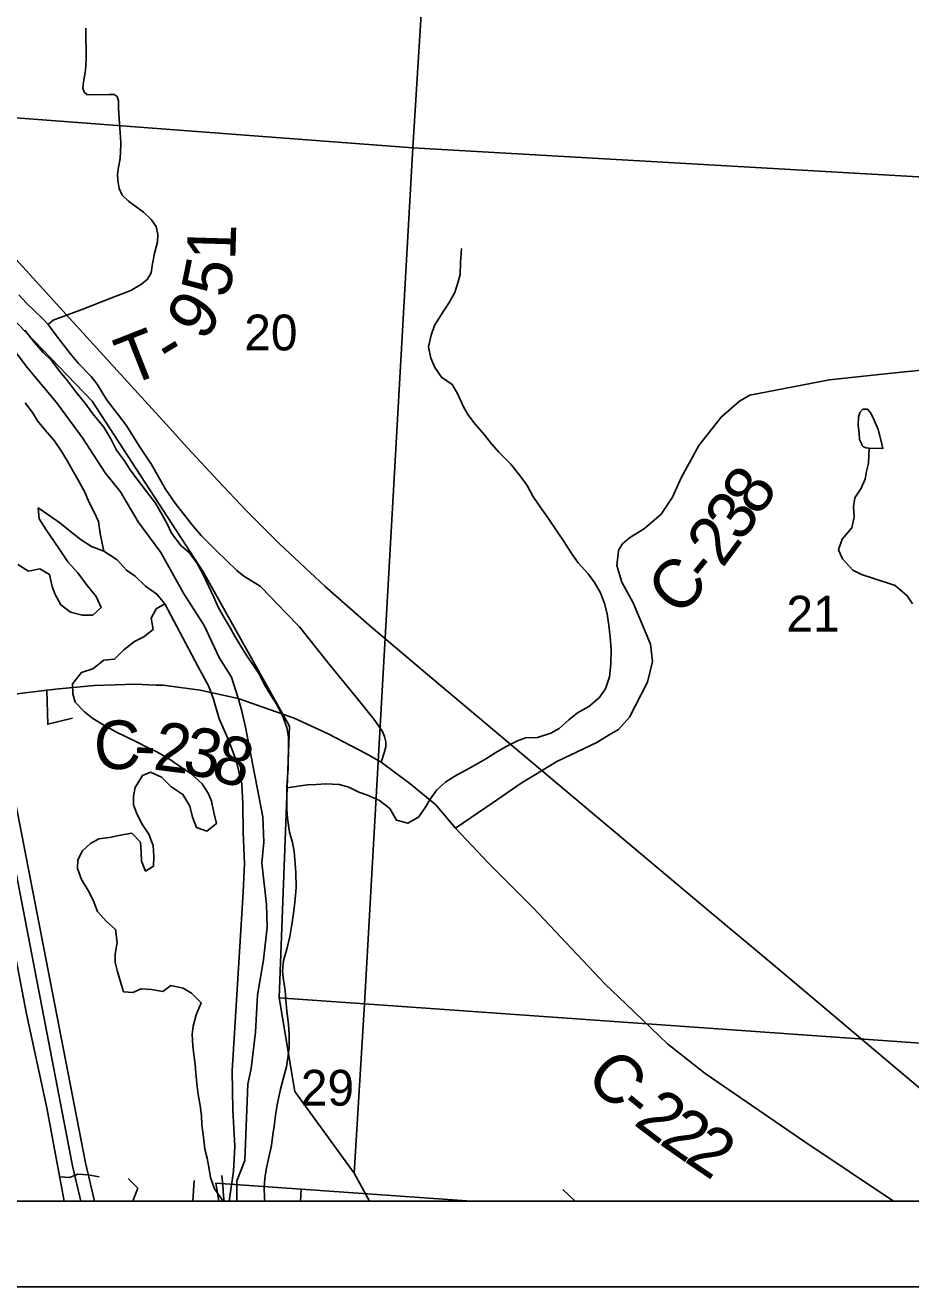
# Model space of a CAD drawing. Extents: x 0 to 34, y 0 to 22.
# Drawn here: x 6.981 to 8.016, y 14 to 15.475 of the extents above; entities that cross this region are included whole.
import ezdxf

# ---------------------------------------------------------------- set-up
doc = ezdxf.new("R2010")
doc.units = 0
for name, color, linetype in [('GM_X_Corporation', 7, 'Continuous'), ('GM_X_County_Road', 7, 'Continuous'), ('GM_X_County_Road_Text', 7, 'Continuous'), ('GM_X_Major_River', 7, 'Continuous'), ('GM_X_Minor_Lake', 7, 'Continuous'), ('GM_X_Minor_River', 7, 'Continuous'), ('GM_X_Rail_Line', 7, 'Continuous'), ('GM_X_Section_Text', 7, 'Continuous'), ('GM_X_Township_Road', 7, 'Continuous'), ('GM_X_Township_Road_Text', 7, 'Continuous'), ('GM_X_US_Route', 7, 'Continuous'), ('SH_Data', 7, 'Continuous')]:
    doc.layers.add(name, color=color, linetype=linetype)

msp = doc.modelspace()

# ---------------------------------------------------------------- linework, layer by layer
at = {"layer": 'GM_X_Corporation'}
for p, q in [((7.1768, 14.1), (7.1783, 14.1242)), ((7.1783, 14.1242), (7.1768, 14.1)), ((7.3032, 14.114), (7.2036, 14.1213)), ((7.3032, 14.114), (7.2036, 14.1213)), ((7.2036, 14.1213), (7.2071, 14.1)), ((7.3024, 14.1), (7.3032, 14.114)), ((7.3032, 14.114), (7.3024, 14.1)), ((7.3032, 14.114), (7.5024, 14.1)), ((7.5024, 14.1), (7.3032, 14.114)), ((2.1, 14.1), (7.1768, 14.1)), ((7.1768, 14.1), (8.9, 14.1)), ((7.2071, 14.1), (7.3024, 14.1)), ((7.3024, 14.1), (7.5024, 14.1)), ((7.5024, 14.1), (8.3035, 14.1))]:
    msp.add_line(p, q, dxfattribs=at)
for points in [[(6.463, 16.4089), (7.4964, 16.3324), (7.434, 15.3319), (6.4021, 15.41)], [(7.4964, 16.3324), (8.4813, 16.2644), (8.4262, 15.2749), (7.434, 15.3319)], [(6.4021, 15.41), (7.434, 15.3319), (7.3773, 14.3307), (7.2777, 14.338), (7.2898, 14.6557), (7.1888, 14.8361), (7.0591, 15.0356), (6.8563, 15.2461), (6.757, 15.3231), (6.6096, 15.301), (6.3846, 15.1464)], [(7.434, 15.3319), (8.4262, 15.2749), (8.3747, 14.2604), (7.3773, 14.3307)], [(7.2777, 14.338), (7.3773, 14.3307), (7.3654, 14.1329), (7.2958, 14.2282)], [(7.3832, 14.1), (8.3589, 14.1), (8.3747, 14.2604), (7.3773, 14.3307), (7.3654, 14.1329)]]:
    msp.add_lwpolyline(points, close=True, dxfattribs=at)
for points in [[(2.1, 14.1), (7.2283, 14.1), (7.228, 14.124), (7.2373, 14.1475), (7.241, 14.237), (7.2449, 14.2552), (7.2498, 14.2976), (7.2524, 14.3409), (7.2595, 14.3825), (7.2636, 14.4204), (7.263, 14.447), (7.2573, 14.4956), (7.2598, 14.5199), (7.2585, 14.5495), (7.2381, 14.6544), (7.2337, 14.6749), (7.2295, 14.6885), (7.2219, 14.7129), (7.2077, 14.7351), (7.1899, 14.7732), (7.1659, 14.8113), (7.1391, 14.8586), (7.1129, 14.8944), (7.092, 14.9295), (7.074, 14.9517), (7.0478, 14.9929), (7.0171, 15.0341), (6.9834, 15.0746), (6.9489, 15.1197)], [(6.9489, 15.1197), (6.9834, 15.0746), (7.0171, 15.0341), (7.0478, 14.9929), (7.074, 14.9517), (7.092, 14.9295), (7.1129, 14.8944), (7.1391, 14.8586), (7.1659, 14.8113), (7.1899, 14.7732), (7.2077, 14.7351), (7.2219, 14.7129), (7.2295, 14.6885), (7.2337, 14.6749), (7.2381, 14.6544), (7.2585, 14.5495), (7.2598, 14.5199), (7.2573, 14.4956), (7.263, 14.447), (7.2636, 14.4204), (7.2595, 14.3825), (7.2524, 14.3409), (7.2498, 14.2976), (7.2449, 14.2552), (7.241, 14.237), (7.2373, 14.1475), (7.228, 14.124), (7.2283, 14.1), (8.9, 14.1)], [(3.0991, 14.1), (7.0261, 14.1), (7.0059, 14.2093), (6.982, 14.3191), (6.9581, 14.4456)]]:
    msp.add_lwpolyline(points, dxfattribs=at)
at = {"layer": 'GM_X_County_Road'}
for points in [[(6.9731, 15.1602), (6.982, 15.1504), (7.0016, 15.1315), (7.0074, 15.1252), (7.0161, 15.1137), (7.033, 15.0914), (7.0431, 15.0796), (7.0577, 15.0645), (7.0649, 15.0555), (7.0703, 15.0466), (7.0756, 15.0376), (7.0988, 15.0075), (7.1151, 14.9817), (7.1284, 14.9618), (7.1446, 14.9326), (7.156, 14.9163), (7.1756, 14.8915), (7.1865, 14.8785), (7.2041, 14.8612), (7.228, 14.8378), (7.2365, 14.831), (7.2556, 14.8193), (7.268, 14.8063), (7.2851, 14.7885), (7.3013, 14.7716), (7.3102, 14.7605), (7.3362, 14.7283), (7.3678, 14.6895), (7.3887, 14.6635), (7.3983, 14.6493), (7.4009, 14.6435), (7.4023, 14.6374), (7.4022, 14.6313), (7.4005, 14.6246), (7.3969, 14.6136)], [(7.6745, 14.8605), (7.6746, 14.8614), (7.6791, 14.8687), (7.6873, 14.8757), (7.705, 14.8866), (7.7245, 14.9036), (7.7378, 14.9236), (7.7477, 14.9461), (7.7684, 14.9837), (7.7945, 15.0171), (7.8159, 15.0357), (7.8283, 15.0427), (7.9213, 15.0605), (7.9902, 15.068), (8.0364, 15.0729), (8.0666, 15.0814), (8.0809, 15.0888), (8.1031, 15.1051), (8.1203, 15.1183)], [(7.6636, 14.6453), (7.6747, 14.6519), (7.6874, 14.6662), (7.7084, 14.7071), (7.7141, 14.7311), (7.7119, 14.7516), (7.6915, 14.7998), (7.6786, 14.8239), (7.6726, 14.8436), (7.6745, 14.8605)], [(6.9681, 14.693), (7.006, 14.6976), (7.02, 14.6993)], [(7.02, 14.6993), (7.0243, 14.6998), (7.0617, 14.703), (7.1094, 14.7047), (7.1338, 14.7037)], [(7.1338, 14.7037), (7.142, 14.7034), (7.1852, 14.6976), (7.2297, 14.688), (7.2753, 14.672)], [(7.2753, 14.672), (7.2951, 14.6651), (7.3343, 14.6472), (7.3797, 14.6231), (7.3969, 14.6136)], [(7.5753, 14.598), (7.6024, 14.6143), (7.6491, 14.6367), (7.6636, 14.6453)], [(7.3969, 14.6136), (7.4303, 14.5887), (7.4607, 14.5637), (7.4837, 14.5365)], [(7.4837, 14.5365), (7.5269, 14.5657), (7.5618, 14.5898), (7.5753, 14.598)], [(7.4837, 14.5365), (7.523, 14.495), (7.5746, 14.4431), (7.6585, 14.3541), (7.6835, 14.3304)], [(7.6835, 14.3304), (7.732, 14.2843), (7.7758, 14.2493), (7.8923, 14.1696), (7.9962, 14.1)]]:
    msp.add_lwpolyline(points, dxfattribs=at)
at = {"layer": 'GM_X_Major_River'}
for p, q in [((7.0215, 14.1284), (7.0325, 14.1277)), ((7.0325, 14.1277), (7.042, 14.1318)), ((7.042, 14.1318), (7.0541, 14.131)), ((7.0541, 14.131), (7.0673, 14.1287)), ((7.101, 14.1268), (7.1124, 14.1154)), ((7.2116, 14.1187), (7.2104, 14.1301)), ((7.1124, 14.1154), (7.1067, 14.1014)), ((7.2127, 14.1058), (7.2116, 14.1187)), ((7.2134, 14.1), (7.2127, 14.1058)), ((7.1067, 14.1014), (7.1063, 14.1))]:
    msp.add_line(p, q, dxfattribs=at)
for points in [[(7.2607, 14.1), (7.2606, 14.1038), (7.2602, 14.1159), (7.261, 14.1265), (7.2625, 14.1372), (7.2652, 14.1497), (7.2686, 14.1652), (7.2702, 14.1781), (7.2717, 14.1879), (7.2733, 14.2004), (7.2752, 14.2126), (7.279, 14.2311), (7.2832, 14.2459), (7.2862, 14.2573), (7.2882, 14.2705), (7.2893, 14.2804), (7.2893, 14.2944), (7.2886, 14.3073), (7.2867, 14.3225), (7.2856, 14.3354), (7.2845, 14.3467), (7.2827, 14.3585), (7.2815, 14.3691), (7.2827, 14.3816), (7.2865, 14.3949), (7.29, 14.4096), (7.2926, 14.4237), (7.2945, 14.4366), (7.2957, 14.4464), (7.2969, 14.4574), (7.2976, 14.4673), (7.2973, 14.4839), (7.2962, 14.4949), (7.2951, 14.509), (7.2932, 14.5196), (7.2898, 14.5317), (7.2872, 14.548), (7.2865, 14.5582), (7.2865, 14.5836), (7.2873, 14.5965), (7.2881, 14.606), (7.2881, 14.6178), (7.2885, 14.6272), (7.2885, 14.6428), (7.2867, 14.6542), (7.2814, 14.6682), (7.2742, 14.6822), (7.2678, 14.6917), (7.2603, 14.7039), (7.2539, 14.7171), (7.2475, 14.7266), (7.2399, 14.738), (7.2316, 14.7513), (7.2256, 14.7608), (7.2199, 14.7714), (7.2128, 14.7831), (7.2063, 14.7949), (7.2011, 14.8063), (7.195, 14.8199), (7.1886, 14.8328), (7.1819, 14.8457), (7.1728, 14.8583), (7.163, 14.8666), (7.1516, 14.8814), (7.1468, 14.8924), (7.1407, 14.9027), (7.1328, 14.9163), (7.1226, 14.93), (7.1124, 14.9433), (7.1026, 14.9565), (7.0966, 14.966), (7.0875, 14.9785), (7.0807, 14.9918), (7.0724, 15.0051), (7.0596, 15.0207), (7.0505, 15.0336), (7.04, 15.0468), (7.0305, 15.059), (7.0211, 15.0704), (7.0113, 15.0833), (7.0018, 15.0928), (6.9916, 15.1042), (6.9803, 15.1186)], [(7.0725, 14.8603), (7.0684, 14.8809), (7.0665, 14.8948), (7.0612, 14.9058), (7.0556, 14.9172), (7.0499, 14.9301), (7.042, 14.9441), (7.036, 14.9551), (7.0299, 14.9654), (7.0228, 14.9775), (7.0145, 14.9896), (7.0039, 15.0018), (6.9948, 15.0128), (6.9892, 15.0223), (6.9805, 15.0337)], [(6.9969, 14.8979), (6.9958, 14.9108), (7.0082, 14.9024), (7.0211, 14.8933), (7.0335, 14.8831), (7.046, 14.8736), (7.0581, 14.8656), (7.0725, 14.8603)], [(6.9718, 14.8445), (6.9846, 14.8369), (6.9979, 14.8395), (7.0092, 14.8331), (7.0122, 14.819), (7.0156, 14.8096), (7.0224, 14.7974), (7.0337, 14.7891), (7.0473, 14.7856), (7.0598, 14.7856), (7.0693, 14.7943), (7.0637, 14.8072), (7.052, 14.8216), (7.0422, 14.8349), (7.0304, 14.8478), (7.021, 14.8619), (7.0146, 14.8717), (7.0052, 14.8854), (6.9969, 14.8979)], [(7.0725, 14.8603), (7.088, 14.85), (7.0989, 14.8379), (7.1091, 14.831), (7.1212, 14.8193), (7.1345, 14.8098), (7.1439, 14.7988)], [(7.1439, 14.7988), (7.1337, 14.7927), (7.128, 14.7821), (7.1302, 14.7688), (7.1192, 14.7601), (7.1086, 14.7548), (7.0961, 14.745), (7.0851, 14.734), (7.0726, 14.7329), (7.0597, 14.7227), (7.0464, 14.7182), (7.0358, 14.7053), (7.0365, 14.6935), (7.0392, 14.6837), (7.0498, 14.6723), (7.0596, 14.6647), (7.0724, 14.6567), (7.0872, 14.6487), (7.0985, 14.643), (7.1106, 14.6373), (7.1227, 14.6309), (7.1337, 14.6259), (7.1481, 14.6179), (7.1624, 14.6081), (7.1745, 14.6001), (7.1877, 14.5883), (7.1945, 14.5773), (7.1983, 14.5678), (7.2013, 14.5546), (7.2043, 14.5417), (7.1929, 14.533), (7.1808, 14.5372), (7.1763, 14.5493), (7.1733, 14.5622), (7.165, 14.5758), (7.151, 14.585), (7.1401, 14.596), (7.1272, 14.6017), (7.1177, 14.5979), (7.1094, 14.5839), (7.1071, 14.5736), (7.1074, 14.5638), (7.1108, 14.5543), (7.1172, 14.5414), (7.1252, 14.5293), (7.1304, 14.516), (7.1312, 14.5035), (7.1308, 14.4917), (7.1213, 14.4861), (7.1168, 14.4978), (7.1164, 14.5084), (7.1153, 14.5198), (7.1055, 14.5304), (7.0922, 14.5282), (7.079, 14.5255), (7.0668, 14.524), (7.057, 14.5184), (7.0475, 14.51), (7.0422, 14.4994), (7.0418, 14.4892), (7.0463, 14.4763), (7.0542, 14.4634), (7.0599, 14.452), (7.0652, 14.4387), (7.0754, 14.4274), (7.0863, 14.4179), (7.0882, 14.4027), (7.0859, 14.3891), (7.0859, 14.3792), (7.0881, 14.3697), (7.0922, 14.3568), (7.0956, 14.3451), (7.1066, 14.3443), (7.1161, 14.3485), (7.1282, 14.3477), (7.1414, 14.3454), (7.1509, 14.3522), (7.1653, 14.3492), (7.1751, 14.3435), (7.1864, 14.3321), (7.1807, 14.3181), (7.1769, 14.3048), (7.1758, 14.2953), (7.1765, 14.2817), (7.178, 14.2718), (7.1795, 14.2604), (7.1802, 14.2498), (7.1817, 14.2343), (7.1828, 14.2248), (7.1851, 14.2119), (7.1866, 14.1998), (7.1873, 14.1895), (7.1892, 14.1748), (7.1907, 14.1611), (7.1933, 14.1505), (7.1952, 14.1399), (7.1974, 14.1278), (7.2019, 14.1145), (7.2122, 14.1)], [(7.219, 14.1), (7.2243, 14.1353), (7.2259, 14.1645), (7.2233, 14.2066), (7.2226, 14.2524), (7.2355, 14.4613), (7.2371, 14.495), (7.2357, 14.5314), (7.235, 14.5644), (7.2339, 14.5883), (7.2275, 14.6156), (7.2181, 14.6406), (7.2076, 14.6641), (7.2008, 14.6872), (7.1952, 14.702), (7.1824, 14.7259), (7.1439, 14.7988)]]:
    msp.add_lwpolyline(points, dxfattribs=at)
at = {"layer": 'GM_X_Minor_Lake'}
for points in [[(7.9676, 14.9808), (7.9838, 14.9804), (7.9812, 14.9906), (7.9782, 15.0024), (7.9737, 15.0134), (7.9695, 15.0217), (7.9658, 15.0263), (7.9601, 15.0263), (7.9567, 15.0225), (7.9552, 15.0168), (7.9548, 15.0077), (7.9559, 14.9979), (7.9562, 14.9907)], [(7.9562, 14.9907), (7.959, 14.9856), (7.9592, 14.9843), (7.9612, 14.9823), (7.9642, 14.981), (7.9676, 14.9808)]]:
    msp.add_lwpolyline(points, dxfattribs=at)
at = {"layer": 'GM_X_Minor_River'}
for points in [[(7.2865, 14.5836), (7.3108, 14.587), (7.321, 14.5874), (7.3323, 14.5881), (7.3479, 14.5874), (7.3592, 14.5843), (7.3709, 14.5786), (7.3811, 14.5748), (7.3948, 14.5687), (7.4069, 14.5592), (7.4148, 14.5456), (7.428, 14.5421), (7.4405, 14.549), (7.4481, 14.5596), (7.4542, 14.5702), (7.4622, 14.5811), (7.4724, 14.5906), (7.483, 14.597), (7.4993, 14.6061), (7.5092, 14.6114), (7.5202, 14.6178), (7.5311, 14.625), (7.5433, 14.6318), (7.5562, 14.6386), (7.5656, 14.642), (7.5796, 14.6424), (7.5955, 14.6473), (7.605, 14.653), (7.6164, 14.6632), (7.6266, 14.6712), (7.6399, 14.6787), (7.652, 14.6889), (7.6592, 14.6992), (7.6638, 14.7132), (7.6657, 14.7283), (7.6658, 14.7454), (7.6647, 14.7602), (7.6632, 14.7735), (7.6613, 14.7871), (7.6583, 14.7992), (7.6534, 14.8114), (7.6463, 14.8235), (7.6391, 14.8338), (7.6274, 14.8467), (7.6198, 14.8573), (7.6108, 14.871), (7.6036, 14.882), (7.5915, 14.9002), (7.5836, 14.9108), (7.5742, 14.9245), (7.5678, 14.937), (7.5591, 14.9487), (7.5485, 14.962), (7.5345, 14.9761), (7.5259, 14.9859), (7.5176, 14.9962), (7.507, 15.0087), (7.4983, 15.0201), (7.493, 15.03), (7.4862, 15.0447), (7.4798, 15.055), (7.4674, 15.0637), (7.4598, 15.0751), (7.4549, 15.0861), (7.4523, 15.0994), (7.4554, 15.1127), (7.4592, 15.124), (7.4664, 15.1354), (7.4763, 15.1509), (7.4831, 15.1627), (7.4865, 15.174), (7.4892, 15.1839), (7.4896, 15.1979), (7.4908, 15.2142)], [(8.0183, 14.7987), (8.0122, 14.8082), (7.9979, 14.82), (7.9718, 14.8288), (7.9589, 14.8329), (7.9487, 14.8379), (7.9366, 14.8512), (7.9317, 14.8618), (7.9363, 14.8743), (7.9473, 14.8876), (7.95, 14.9004), (7.9492, 14.9122), (7.9508, 14.9228), (7.958, 14.933), (7.9629, 14.9444), (7.9645, 14.9539), (7.9668, 14.9633), (7.9676, 14.9808)]]:
    msp.add_lwpolyline(points, dxfattribs=at)
at = {"layer": 'GM_X_Rail_Line'}
msp.add_lwpolyline([(8.1762, 14.1), (8.145, 14.1295), (8.1078, 14.1631), (8.0715, 14.1949), (7.9931, 14.2608), (7.8607, 14.3721), (7.7807, 14.4392), (7.5442, 14.6377), (7.4488, 14.7181), (7.3828, 14.7736), (7.3313, 14.8189), (7.278, 14.8689), (7.2388, 14.9081), (7.2061, 14.9425), (7.1705, 14.981), (7.1453, 15.0088), (7.0716, 15.0894), (6.9457, 15.2275)], dxfattribs=at)
at = {"layer": 'GM_X_Township_Road'}
msp.add_line((7.6094, 14.1137), (7.6239, 14.1), dxfattribs=at)
for points in [[(7.0924, 15.3384), (7.091, 15.3603), (7.0899, 15.3782), (7.0897, 15.3871), (7.0881, 15.3919), (7.0846, 15.3943), (7.0787, 15.3945), (7.0566, 15.3938), (7.0527, 15.3945), (7.0497, 15.3972), (7.048, 15.4016), (7.0486, 15.4092), (7.0511, 15.4224), (7.052, 15.4348), (7.0514, 15.472)], [(7.0074, 15.1252), (7.0132, 15.1304), (7.0479, 15.1434), (7.0809, 15.1563), (7.1042, 15.1652), (7.1167, 15.1724), (7.1236, 15.1783), (7.128, 15.1856), (7.1292, 15.1938), (7.132, 15.2087), (7.1353, 15.2215), (7.1357, 15.2305), (7.1336, 15.2399), (7.128, 15.248), (7.1191, 15.2566), (7.1013, 15.2697), (7.0941, 15.2767), (7.0906, 15.2846), (7.0889, 15.2936), (7.0884, 15.301), (7.0896, 15.3092), (7.0915, 15.3195), (7.0926, 15.3354), (7.0924, 15.3384)], [(7.0359, 14.6651), (7.0069, 14.6579), (7.006, 14.6976)]]:
    msp.add_lwpolyline(points, dxfattribs=at)
at = {"layer": 'GM_X_US_Route'}
for points in [[(7.0457, 14.1), (7.0359, 14.1414), (6.9523, 14.5748), (6.931, 14.6844), (6.9181, 14.7488), (6.9126, 14.7751), (6.9074, 14.7924), (6.897, 14.8232), (6.8902, 14.8404), (6.8794, 14.8609), (6.866, 14.8851), (6.847, 14.9114), (6.8249, 14.9388), (6.7925, 14.9688), (6.7491, 15.0054), (6.6804, 15.0633), (6.6328, 15.1041), (6.4401, 15.2668), (6.3954, 15.3044), (6.3704, 15.326), (6.3346, 15.3528), (6.2941, 15.3773), (6.2706, 15.3887)], [(7.0618, 14.1), (7.0512, 14.1448), (6.969, 14.5687)]]:
    msp.add_lwpolyline(points, dxfattribs=at)
at = {"layer": 'SH_Data'}
for p, q in [((2.1, 14.1), (8.9, 14.1)), ((2, 14), (9, 14))]:
    msp.add_line(p, q, dxfattribs=at)

# ---------------------------------------------------------------- texts
at = {"layer": 'GM_X_County_Road_Text'}
for s, rotation, p in [('8', 56.5422, (7.8388, 14.8992)), ('3', 55.3635, (7.8181, 14.8693)), ('2', 53.3592, (7.796, 14.8395)), ('C', 47.0482, (7.745, 14.782)), ('-', 50.5702, (7.7793, 14.8191)), ('C', 1.534, (7.0616, 14.6047)), ('2', 352.7736, (7.1292, 14.6051)), ('3', 349.0197, (7.163, 14.6008)), ('8', 342.406, (7.1957, 14.5946)), ('-', 357.6108, (7.1072, 14.6059)), ('C', 316.0101, (7.6338, 14.2425)), ('-', 320.6383, (7.6711, 14.2068)), ('2', 322.6446, (7.6909, 14.1906)), ('2', 325.0931, (7.7208, 14.1678)), ('2', 325.7428, (7.7501, 14.1474))]:
    msp.add_text(s, height=0.0568, rotation=rotation, dxfattribs=at).set_placement(p)
at = {"layer": 'GM_X_Section_Text'}
for s, p in [('20', (7.2368, 15.0951)), ('21', (7.8709, 14.7662)), ('29', (7.303, 14.2118))]:
    msp.add_text(s, height=0.04186, rotation=0, dxfattribs=at).set_placement(p)
at = {"layer": 'GM_X_Township_Road_Text'}
for s, rotation, p in [('1', 88.3412, (7.2263, 15.1999)), ('5', 78.384, (7.218, 15.1549)), ('9', 56.4062, (7.1896, 15.104)), ('T', 21.4966, (7.1012, 15.0529)), ('-', 31.2816, (7.1502, 15.0732))]:
    msp.add_text(s, height=0.0568, rotation=rotation, dxfattribs=at).set_placement(p)

doc.saveas('drawing.dxf')
